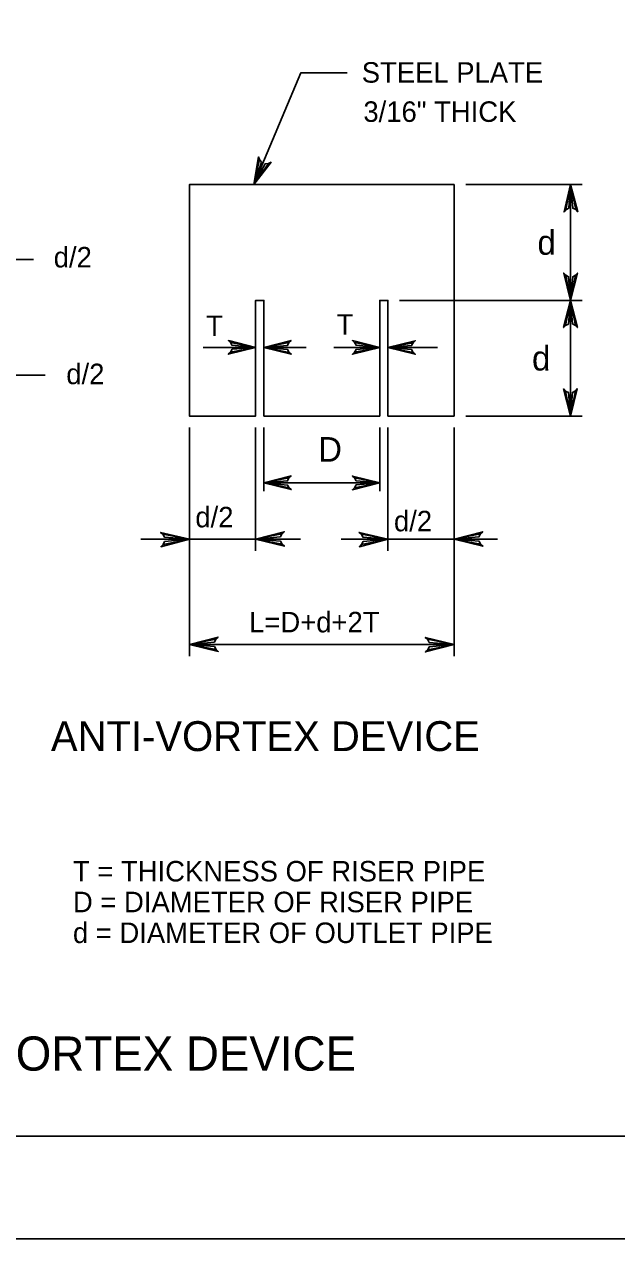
# Model space of a CAD drawing. Extents: x 636462 to 639890, y 299944 to 300538.
# Drawn here: x 637797.1 to 637883.7, y 299944.4 to 300122 of the extents above; entities that cross this region are included whole.
import ezdxf

# ---------------------------------------------------------------- set-up
doc = ezdxf.new("R2010")
doc.units = 0
for name, color, linetype in [('1', 7, 'Continuous'), ('Default', 7, 'Continuous'), ('PLT-BNDY', 7, 'Continuous')]:
    doc.layers.add(name, color=color, linetype=linetype)

msp = doc.modelspace()

# ---------------------------------------------------------------- linework, layer by layer
at = {"layer": '1'}
msp.add_lwpolyline([(638128.91, 299959.45), (638128.91, 300523.45), (637342.91, 300523.45), (637342.91, 299959.45), (638128.91, 299959.45), (638128.91, 299985.81), (637928.91, 299985.81), (637928.91, 300050.49), (638128.91, 300050.49), (638128.91, 300079.45), (637928.91, 300079.45), (637928.91, 299959.45), (638007.72, 299959.45), (638007.72, 299985.81), (638007.72, 299959.45), (638084.72, 299959.45), (638084.72, 299985.81), (638084.72, 299973.49), (638128.91, 299973.49)], dxfattribs=at)
at = {"layer": 'Default'}
for p, q in [((637861.62, 300098.56), (637878.63, 300098.56)), ((637851.95, 300081.64), (637878.63, 300081.64)), ((637830.92, 300079.95), (637830.92, 300073.06)), ((637832.13, 300079.95), (637832.13, 300073.06)), ((637849.05, 300079.95), (637849.05, 300073.06)), ((637850.26, 300079.95), (637850.26, 300073.06)), ((637861.62, 300064.72), (637878.63, 300064.72)), ((637821.25, 300063.03), (637821.25, 300029.63)), ((637821.25, 300063.03), (637821.25, 300045.04)), ((637830.92, 300063.03), (637830.92, 300045.04)), ((637832.13, 300063.03), (637832.13, 300053.73)), ((637849.05, 300063.03), (637849.05, 300053.73)), ((637850.26, 300063.03), (637850.26, 300045.04)), ((637859.93, 300063.03), (637859.93, 300029.63)), ((637859.93, 300063.03), (637859.93, 300045.04)), ((637814.15, 300046.73), (637821.25, 300046.73)), ((637830.92, 300046.73), (637821.25, 300046.73)), ((637830.92, 300046.73), (637837.49, 300046.73)), ((637843.42, 300046.73), (637850.26, 300046.73)), ((637850.26, 300046.73), (637859.93, 300046.73)), ((637859.93, 300046.73), (637866.29, 300046.73))]:
    msp.add_line(p, q, dxfattribs=at)
for points in [[(637830.67, 300098.56), (637837.52, 300114.89), (637844.32, 300114.89)], [(637832.81, 300101.65), (637833.17, 300101.83), (637830.67, 300098.56), (637832.81, 300101.65), (637832.33, 300101.61), (637830.67, 300098.56), (637831.78, 300101.85), (637831.47, 300102.21), (637830.67, 300098.56), (637831.34, 300102.62), (637831.47, 300102.21)], [(637859.93, 300098.56), (637821.25, 300098.56), (637821.25, 300064.72), (637830.92, 300064.72), (637830.92, 300081.64), (637832.13, 300081.64), (637832.13, 300064.72), (637849.05, 300064.72), (637849.05, 300081.64), (637850.26, 300081.64), (637850.26, 300064.72), (637859.93, 300064.72), (637859.93, 300098.56)], [(637876.25, 300094.87), (637876, 300094.56), (637876.94, 300098.56), (637876.25, 300094.87), (637876.68, 300095.1), (637876.94, 300098.56), (637877.27, 300095.11), (637877.7, 300094.91), (637876.94, 300098.56), (637877.99, 300094.59), (637877.7, 300094.91)], [(637876.94, 300081.64), (637876.94, 300098.56)], [(637798.44, 300087.62), (637793.6, 300087.62), (637786.63, 300088.82)], [(637877.69, 300085.32), (637877.95, 300085.63), (637876.94, 300081.64), (637877.69, 300085.32), (637877.26, 300085.1), (637876.94, 300081.64), (637876.67, 300085.1), (637876.24, 300085.31), (637876.94, 300081.64), (637875.95, 300085.63), (637876.24, 300085.31)], [(637876.2, 300077.96), (637875.94, 300077.65), (637876.94, 300081.64), (637876.2, 300077.96), (637876.63, 300078.18), (637876.94, 300081.64), (637877.22, 300078.19), (637877.65, 300077.98), (637876.94, 300081.64), (637877.94, 300077.66), (637877.65, 300077.98)], [(637876.94, 300081.64), (637876.94, 300064.72)], [(637827.24, 300075.5), (637826.94, 300075.76), (637830.92, 300074.75), (637827.24, 300075.5), (637827.46, 300075.07), (637830.92, 300074.75), (637827.47, 300074.48), (637827.25, 300074.05), (637830.92, 300074.75), (637826.93, 300073.76), (637827.25, 300074.05)], [(637835.81, 300074.03), (637836.12, 300073.77), (637832.13, 300074.75), (637835.81, 300074.03), (637835.59, 300074.45), (637832.13, 300074.75), (637835.58, 300075.05), (637835.79, 300075.48), (637832.13, 300074.75), (637836.11, 300075.77), (637835.79, 300075.48)], [(637845.37, 300075.49), (637845.06, 300075.75), (637849.05, 300074.75), (637845.37, 300075.49), (637845.59, 300075.07), (637849.05, 300074.75), (637845.6, 300074.47), (637845.39, 300074.04), (637849.05, 300074.75), (637845.06, 300073.75), (637845.39, 300074.04)], [(637853.94, 300074), (637854.24, 300073.75), (637850.26, 300074.75), (637853.94, 300074), (637853.72, 300074.43), (637850.26, 300074.75), (637853.71, 300075.02), (637853.93, 300075.45), (637850.26, 300074.75), (637854.25, 300075.74), (637853.93, 300075.45)], [(637830.92, 300074.75), (637823.27, 300074.75)], [(637832.13, 300074.75), (637838.32, 300074.75)], [(637849.05, 300074.75), (637842.35, 300074.75)], [(637850.26, 300074.75), (637857.52, 300074.75)], [(637800.14, 300070.72), (637795.31, 300070.72), (637792.89, 300070.72), (637786.65, 300072.04)], [(637877.65, 300068.41), (637877.9, 300068.72), (637876.94, 300064.72), (637877.65, 300068.41), (637877.23, 300068.18), (637876.94, 300064.72), (637876.63, 300068.17), (637876.2, 300068.38), (637876.94, 300064.72), (637875.91, 300068.7), (637876.2, 300068.38)], [(637835.81, 300054.22), (637836.12, 300053.97), (637832.13, 300054.95), (637835.81, 300054.22), (637835.59, 300054.64), (637832.13, 300054.95), (637835.58, 300055.24), (637835.79, 300055.67), (637832.13, 300054.95), (637836.11, 300055.96), (637835.79, 300055.67)], [(637845.37, 300055.68), (637845.06, 300055.94), (637849.05, 300054.95), (637845.37, 300055.68), (637845.59, 300055.26), (637849.05, 300054.95), (637845.6, 300054.66), (637845.39, 300054.23), (637849.05, 300054.95), (637845.07, 300053.94), (637845.39, 300054.23)], [(637832.13, 300054.95), (637841.2, 300054.95)], [(637849.05, 300054.95), (637840.93, 300054.95)], [(637817.36, 300047.46), (637817.04, 300047.72), (637821.25, 300046.73), (637817.36, 300047.46), (637817.61, 300047.01), (637821.25, 300046.73), (637817.62, 300046.38), (637817.41, 300045.93), (637821.25, 300046.73), (637817.07, 300045.62), (637817.41, 300045.93)], [(637834.8, 300045.98), (637835.13, 300045.71), (637830.92, 300046.73), (637834.8, 300045.98), (637834.56, 300046.43), (637830.92, 300046.73), (637834.55, 300047.06), (637834.77, 300047.51), (637830.92, 300046.73), (637835.11, 300047.81), (637834.77, 300047.51)], [(637846.37, 300047.46), (637846.05, 300047.72), (637850.26, 300046.73), (637846.37, 300047.46), (637846.61, 300047.01), (637850.26, 300046.73), (637846.63, 300046.38), (637846.41, 300045.93), (637850.26, 300046.73), (637846.08, 300045.62), (637846.41, 300045.93)], [(637863.81, 300045.98), (637864.13, 300045.71), (637859.93, 300046.73), (637863.81, 300045.98), (637863.57, 300046.43), (637859.93, 300046.73), (637863.56, 300047.06), (637863.78, 300047.51), (637859.93, 300046.73), (637864.12, 300047.81), (637863.78, 300047.51)], [(637825.13, 300030.58), (637825.46, 300030.31), (637821.25, 300031.32), (637825.13, 300030.58), (637824.89, 300031.02), (637821.25, 300031.32), (637824.89, 300031.65), (637825.1, 300032.1), (637821.25, 300031.32), (637825.44, 300032.41), (637825.1, 300032.1)], [(637856.05, 300032.08), (637855.72, 300032.34), (637859.93, 300031.32), (637856.05, 300032.08), (637856.29, 300031.63), (637859.93, 300031.32), (637856.3, 300031), (637856.08, 300030.55), (637859.93, 300031.32), (637855.74, 300030.24), (637856.08, 300030.55)], [(637821.25, 300031.32), (637839.73, 300031.32)], [(637859.93, 300031.32), (637839.73, 300031.32)]]:
    msp.add_lwpolyline(points, dxfattribs=at)
at = {"layer": 'PLT-BNDY'}
msp.add_lwpolyline([(637302.91, 300538.45), (638143.91, 300538.45), (638143.91, 299944.45), (637302.91, 299944.45)], close=True, dxfattribs=at)

# ---------------------------------------------------------------- texts
at = {"layer": 'Default'}
for s, height, p in [('STEEL PLATE', 2.9979, (637846.43, 300113.46)), ('3/16" THICK', 2.9979, (637846.67, 300107.73)), ('d', 3.6, (637872.11, 300088.3)), ('d/2', 2.998, (637801.41, 300086.45)), ('T', 3, (637823.69, 300076.42)), ('T', 3, (637842.75, 300076.61)), ('d', 3.6, (637871.32, 300071.38)), ('d/2', 2.998, (637803.25, 300069.38)), ('D', 3.6, (637840.06, 300058.05)), ('d/2', 2.998, (637822.11, 300048.45)), ('d/2', 2.998, (637851.14, 300047.87)), ('L=D+d+2T', 2.998, (637829.97, 300033.1)), ('ANTI-VORTEX DEVICE', 4.3721, (637801, 300015.74)), ('T = THICKNESS OF RISER PIPE', 2.998, (637804.22, 299996.68)), ('D = DIAMETER OF RISER PIPE', 2.998, (637804.22, 299992.18)), ('d = DIAMETER OF OUTLET PIPE', 2.998, (637804.22, 299987.68)), ('TRASH RACK AND ANTI-VORTEX DEVICE', 4.9967, (637713.07, 299969.02))]:
    msp.add_text(s, height=height, dxfattribs=at).set_placement(p)

doc.saveas('drawing.dxf')
